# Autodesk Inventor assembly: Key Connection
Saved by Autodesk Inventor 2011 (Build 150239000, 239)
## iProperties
Created: 2011-05
Part Number: Key Connection
Document SubType Name: Assembly
Designer: 904Chiaki
ClientObjectVersion: 1
Author: 904Chiaki
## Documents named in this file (2)
- E:\2.FINISH\DOAN_CTM_final\Lap1_codai\Design Accelerator\Key Connection3.iam
- C:\Users\HTYCOON\Documents\Inventor\Content Center Files\R2011\en-US\ISO 2491 - A\ISO 2491 - A  22 x 9 x 63.ipt
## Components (1 placed, 1 different names)
1. ISO 2491 A A  22 x 9 x 63:1
